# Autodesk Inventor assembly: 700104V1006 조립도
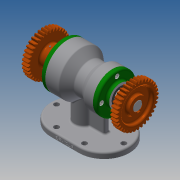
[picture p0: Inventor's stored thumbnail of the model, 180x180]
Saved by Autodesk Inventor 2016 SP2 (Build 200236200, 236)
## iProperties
Created: 2020-01
Part Number: 700104V1006 조립도
Document SubType Name: Assembly
Designer: EZ
Author: EZ
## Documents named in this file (13)
- C:\Users\EZ\Desktop\700104V1006\700104V1006 조립도.iam
- C:\Users\EZ\Desktop\700104V1006\본체.ipt
- C:\Users\EZ\Desktop\700104V1006\축.ipt
- C:\Users\EZ\Desktop\700104V1006\키 5 x 5 x 18.ipt
- C:\Users\EZ\Desktop\700104V1006\베어링 6203.ipt
- C:\Users\EZ\Desktop\700104V1006\베어링 6205.ipt
- C:\Users\EZ\Desktop\700104V1006\뒤커버.ipt
- C:\Users\EZ\Desktop\700104V1006\앞커버.ipt
- C:\Users\EZ\Desktop\700104V1006\오일 실 17 30 8.ipt
- C:\Users\EZ\Desktop\700104V1006\오일 실 25 38 8.ipt
- C:\Users\EZ\Desktop\700104V1006\볼트 M4.ipt
- C:\Users\EZ\Desktop\700104V1006\스퍼기어.ipt
- C:\Users\EZ\Desktop\700104V1006\멈춤나사 M3.ipt
